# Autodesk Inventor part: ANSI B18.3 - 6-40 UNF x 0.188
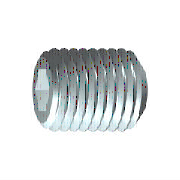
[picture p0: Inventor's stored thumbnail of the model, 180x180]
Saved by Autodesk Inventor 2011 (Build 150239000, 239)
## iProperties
IsCustomPart: 0
Created: 2008-02
Part Number: ANSI B18.3 - 6-40 UNF x 0.188
Material: Steel, Mild
Description: Hexagon Socket Set Screw - Flat Point
Document SubType Name: Modeling
Standard: ANSI B18.3
Standard Revision: 2003
Standards Organization: ANSI
Language: en-US
Size Designation: 6-40 UNF x 0.188
Categories: <MemberInstance><Categories><Category DisplayName="Fasteners" InternalName="e4da775c-781d-43d5-af7c-5136215cf5a6" Mnemonic="FSTN"><Category DisplayName="Bolts"
Density: 7.86 g/cm^3
Mass: 0.312247 g
Surface Area: 0.781327 cm^2
Volume: 0.0397261 cm^3
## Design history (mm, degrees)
revolve "Body" stored, may be unused: angle "d6" = 90 deg
sketch "Sketch2"
  geometry: L1 (-0.455, 0.787)-(0.455, 0.787); L2 (0.455, 0.787)-(0.909, 0); L3 (0.909, 0)-(0.455, -0.787); L4 (0.455, -0.787)-(-0.455, -0.787); L5 (-0.455, -0.787)-(-0.909, 0); L6 (-0.909, 0)-(-0.455, 0.787); A1 r 0.909 centre (0, 0) between (-0.455, 0.787) and (0.455, 0.787) reference; 2 further points
  constraints: 12 end point, 2 point on circle, 1 coincident, 1 horizontal, 11 other
extrude "Slot" join sketch "Sketch2" taper "d9" = 0 deg; stored distance "d21" = 10
workaxis "Work Axis1"
workplane "Work Plane1"
body "Solid1"
chamfer "Chamfer1" distance "d7" = 0.38953 (= -0.5 x GD1 + 0.5 x NND); stored, may be unused: angle "d8" = 45 deg (= FAWI), second distance "d29" = 0.38953 (= -0.5 x GD1 + 0.5 x NND)
feature "Thread" dims "d11" = 4.7752 (= NLG), "d12" = 0
chamfer "Chamfer2" distance "d13" = 0.38953 (= -0.5 x GD1 + 0.5 x NND); stored, may be unused: angle "d14" = 45 deg (= FAWI), second distance "d30" = 0.38953 (= -0.5 x GD1 + 0.5 x NND)
sketch "Sketch1"
  geometry: L1 (0, 0)-(2.218, 0); L2 (4.775, 0.909)-(4.775, 1.753); L3 (4.775, 1.753)-(0, 1.753); L4 (4.775, 0.909)-(2.743, 0.909); L5 (2.743, 0.909)-(2.218, 0); L6 (0, -0.351)-(0, 2.103) reference; L7 (0, 1.753)-(0, 0)
  constraints: 13 end point, 3 parallel, 1 collinear, 1 perpendicular, 1 point on line
  dimensions: "d0" = 2.032 distance of L2.start L4.end (= INTI); "d1" = 60 deg angle of L5 L1; "d2" = 3.5052 diameter of L3 L1 (= NND); "d3" = 1.81842 diameter of L4 L1 (= 1.1547 x SW); "d5" = 4.7752 distance from line of L2 L3.end (= NLG)
other parameters: "NND" = 3.5052 [user parameter; used in 5 equation terms], "NLG" = 4.7752 [user parameter; used in 2 equation terms], "INTI" = 2.032 [user parameter; used in 1 equation term], "FAWI" = 45 deg [user parameter; used in 2 equation terms], "SW" = 1.5748 [user parameter; used in 2 equation terms], "GD1" = 2.72613 [user parameter; used in 4 equation terms], "d4" = 0, "FAWI1" = 45 deg [user parameter], "d15" = 0, "d31" = 0, "SPD" = 1.8796 [user parameter], "SEWI" = 90 deg [user parameter], "TOA" = 30 deg [user parameter], "ZLG" = 0.9652 [user parameter], "ZD" = 2.3368 [user parameter], "HHPTC" = 0.635 [user parameter], "PTC" = 0.635 (computed from TPU) [user parameter], "THREADDIA" = 3.5052 [user parameter], "OPR" = 2.6416 [user parameter], "E0" = 1.81889 (= 1.155 x SW) [user parameter]
